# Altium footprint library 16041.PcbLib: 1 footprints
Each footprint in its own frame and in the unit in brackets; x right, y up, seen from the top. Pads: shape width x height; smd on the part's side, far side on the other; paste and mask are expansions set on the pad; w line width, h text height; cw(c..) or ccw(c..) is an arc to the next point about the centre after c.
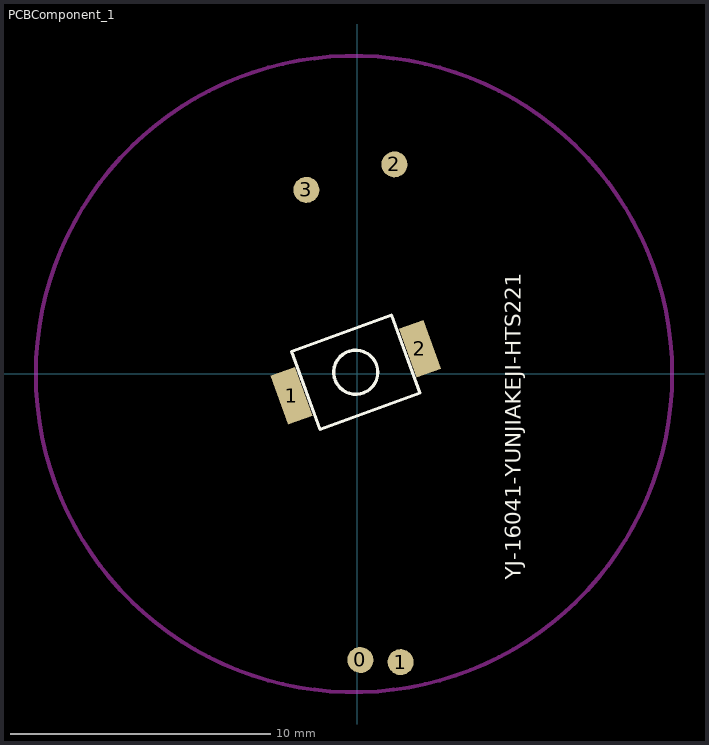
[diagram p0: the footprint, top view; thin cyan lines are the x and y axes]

## PCBComponent_1 [mm]
pads (6):
  round 1 smd: 0(0.12,-11.014) 1(1.67,-11.094) 2(1.43,8.066) 3(-1.96,7.086)
  rect 2x1 smd rot 110: 1(-2.528,-0.84) 2(2.412,0.968)
Top Overlay:
  circle w0.127: c-0.058,0.064 r0.85
  lines w0.127: -2.531,0.867 -1.437,-2.14 2.416,-0.738 1.321,2.269 -2.531,0.867
  text "YJ-16041-YUNJIAKEJI-HTS221" at 6.3,-7.934 h0.6
Keep-Out Layer:
  circle w0.152: c-0.126,-0.003 r12.25
3D body: height 1.8, standoff 0, extent -2.537,-2.143 2.424,2.272
3D body: height 0.1, standoff 0, extent 1.567,-0.028 3.023,1.869
3D body: height 0.1, standoff 0, extent -3.171,-1.752 -1.715,0.144
3D body: height 2.3, standoff 1.8, extent -1.33,-1.212 1.225,1.345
